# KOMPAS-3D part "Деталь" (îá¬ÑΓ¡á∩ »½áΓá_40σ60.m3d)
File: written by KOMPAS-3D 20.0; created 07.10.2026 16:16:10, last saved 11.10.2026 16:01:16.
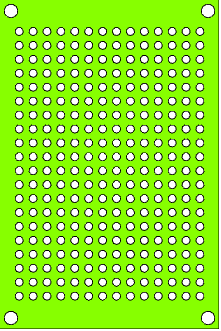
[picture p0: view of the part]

Document properties: Полное имя файла: D:\myProjects\Progect_esp32\box_compas\Макетная плата_40х60.m3d

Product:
- Part/product: Деталь
    Масса: 0.0222195

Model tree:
1. Эскиз:1
2. Элемент выдавливания:1
     Расстояние 1 = 1.5
3. Эскиз:2  (with: Элемент выдавливания:1)
4. Элемент выдавливания:2
     Расстояние 2 = 1.5
5. Эскиз:3  (with: Элемент выдавливания:1)
6. Элемент выдавливания:3
     Расстояние 2 = 1.5
7. Массив по сетке:1  (with: Элемент выдавливания:3, Эскиз:3, Элемент выдавливания:1)  (280 pattern instances)
     Шаг 1 = 2.54; Угол раствора = -90; Шаг 2 = 2.54
8. Массив по сетке:2  (with: Элемент выдавливания:2, Эскиз:2, Элемент выдавливания:1)  (4 pattern instances)
     Шаг 1 = 56; Угол раствора = 90; Шаг 2 = 36; Геометрический массив = 128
